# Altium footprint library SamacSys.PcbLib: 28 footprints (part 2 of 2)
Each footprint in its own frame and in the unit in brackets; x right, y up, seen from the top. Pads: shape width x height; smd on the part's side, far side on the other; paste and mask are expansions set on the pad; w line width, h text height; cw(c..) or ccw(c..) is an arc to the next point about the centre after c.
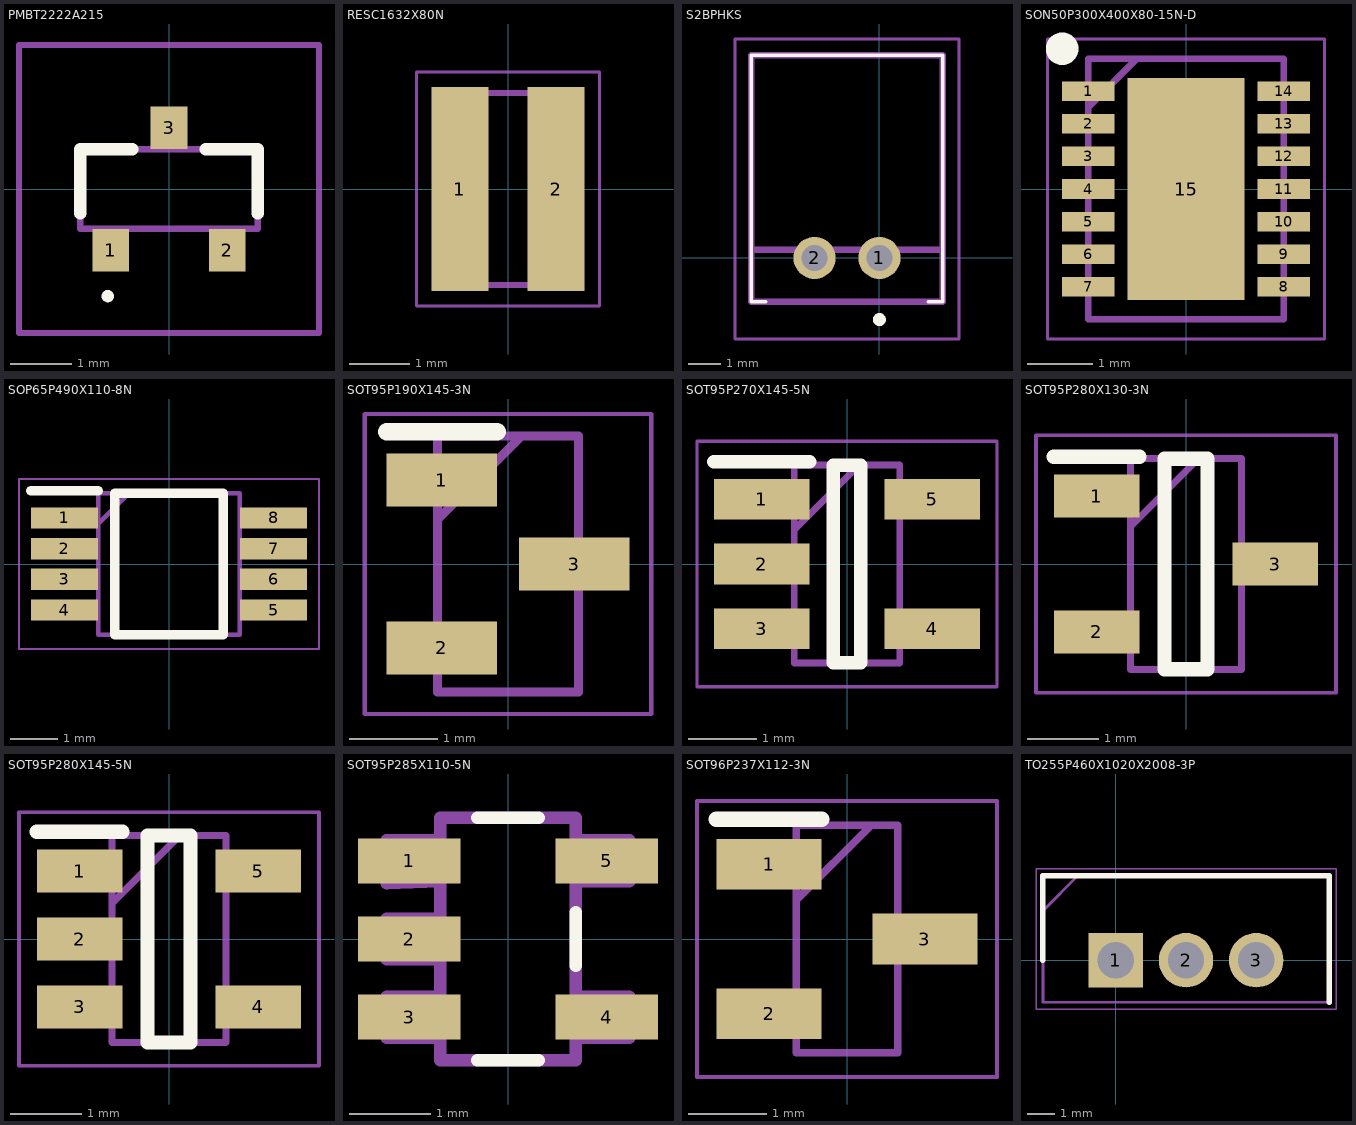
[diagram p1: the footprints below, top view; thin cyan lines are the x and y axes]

## PMBT2222A215 [mm]
pads (3):
  rect 0.6x0.7 smd: 1(-0.95,-1) 2(0.95,-1) 3(0,1)
Top Overlay:
  lines w0.1: -1,-1.8 cw(c-1,-1.75) -1,-1.7 cw(c-1,-1.75) -1,-1.8
  lines w0.2: -1.45,-0.4 -1.45,0.65 -0.6,0.65 ; 0.6,0.65 1.45,0.65 1.45,-0.4
Mechanical 13:
  lines w0.1: -1.45,-0.65 -1.45,0.65 1.45,0.65 1.45,-0.65 -1.45,-0.65
Mechanical 15:
  lines w0.1: -2.45,-2.35 -2.45,2.35 2.45,2.35 2.45,-2.35 -2.45,-2.35
3D body "PMBT2222A,215.stp": height 0.95, standoff 0, extent -1.452,-1.201 1.448,1.199

## RESC1632X80N [mm]
pads (2):
  rect 0.95x3.4 smd: 1(-0.8,0) 2(0.8,0)
Mechanical 13:
  lines w0.1: -0.8,-1.6 -0.8,1.6 0.8,1.6 0.8,-1.6 -0.8,-1.6
Mechanical 15:
  lines w0.05: -1.525,-1.95 -1.525,1.95 1.525,1.95 1.525,-1.95 -1.525,-1.95
3D body "WFCP0612R0150FE66.stp": height 0.8, standoff 0, extent -0.8,-1.6 0.8,1.6

## S2BPHKS [mm]
pads (2):
  round 1.3 hole 0.8: 1(0,0) 2(-2,0)
Top Overlay:
  lines w0.1: -3.5,-1.35 -3.95,-1.35 -3.95,6.25 1.95,6.25 1.95,-1.35 1.5,-1.35
  lines w0.2: -0.1,-1.9 cw(c0,-1.9) 0.1,-1.9 cw(c0,-1.9) -0.1,-1.9
Mechanical 13:
  lines w0.2: -3.95,0.25 -3.95,-1.35 1.95,-1.35 1.95,0.25 ; -3.95,0.25 1.95,0.25 ; -3.95,0.25 -3.95,6.25 1.95,6.25 1.95,0.25 ; -3.95,0.25 1.95,0.25
Mechanical 15:
  lines w0.1: -4.45,-2.5 -4.45,6.75 2.45,6.75 2.45,-2.5 -4.45,-2.5
3D body "S2B-PH-K-S.stp": height 4.9, standoff -5, extent -3.95,-1.35 1.95,6.25

## SON50P300X400X80-15N-D [mm]
pads (15):
  rect 0.8x0.3 smd: 1(-1.5,1.5) 2(-1.5,1) 3(-1.5,0.5) 4(-1.5,0) 5(-1.5,-0.5) 6(-1.5,-1) 7(-1.5,-1.5) 8(1.5,-1.5) 9(1.5,-1) 10(1.5,-0.5) 11(1.5,0) 12(1.5,0.5) 13(1.5,1) 14(1.5,1.5)
  rect 1.8x3.4 smd: 15(0,0)
Top Overlay:
  circle w0.25: c-1.9,2.15 r0.125
Mechanical 13:
  lines w0.1: -1.5,1.25 -0.75,2 ; -1.5,-2 -1.5,2 1.5,2 1.5,-2 -1.5,-2
Mechanical 15:
  lines w0.05: -2.125,-2.3 -2.125,2.3 2.125,2.3 2.125,-2.3 -2.125,-2.3
3D body "LTC3533EDE#TRPBF.stp": height 0.8, standoff 0, extent -1.55,-2 1.55,2

## SOP65P490X110-8N [mm]
pads (8):
  rect 1.425x0.45 smd: 1(-2.212,0.975) 2(-2.212,0.325) 3(-2.212,-0.325) 4(-2.212,-0.975) 5(2.212,-0.975) 6(2.212,-0.325) 7(2.212,0.325) 8(2.212,0.975)
Top Overlay:
  lines w0.2: -2.925,1.55 -1.5,1.55 ; -1.15,-1.5 -1.15,1.5 1.15,1.5 1.15,-1.5 -1.15,-1.5
Mechanical 13:
  lines w0.1: -1.5,0.85 -0.85,1.5 ; -1.5,-1.5 -1.5,1.5 1.5,1.5 1.5,-1.5 -1.5,-1.5
Mechanical 15:
  lines w0.05: -3.175,-1.8 -3.175,1.8 3.175,1.8 3.175,-1.8 -3.175,-1.8
3D body "DS2745U+.stp": height 1.1, standoff 0, extent -2.452,-1.5 2.452,1.5

## SOT95P190X145-3N [mm]
pads (3):
  rect 1.25x0.6 smd: 1(-0.75,0.95) 2(-0.75,-0.95) 3(0.75,0)
Top Overlay:
  lines w0.2: -1.375,1.5 -0.125,1.5
Mechanical 13:
  lines w0.1: -0.8,0.5 0.15,1.45 ; -0.8,-1.45 -0.8,1.45 0.8,1.45 0.8,-1.45 -0.8,-1.45
Mechanical 15:
  lines w0.05: -1.625,-1.7 -1.625,1.7 1.625,1.7 1.625,-1.7 -1.625,-1.7
3D body "HT7750A_SOT23-3.stp": height 1.1, standoff 0, extent -1.3,-1.35 1.3,1.35

## SOT95P270X145-5N [mm]
pads (5):
  rect 1.4x0.6 smd: 1(-1.25,0.95) 2(-1.25,0) 3(-1.25,-0.95) 4(1.25,-0.95) 5(1.25,0.95)
Top Overlay:
  lines w0.2: -1.95,1.5 -0.55,1.5 ; -0.2,-1.45 -0.2,1.45 0.2,1.45 0.2,-1.45 -0.2,-1.45
Mechanical 13:
  lines w0.1: -0.775,0.5 0.175,1.45 ; -0.775,-1.45 -0.775,1.45 0.775,1.45 0.775,-1.45 -0.775,-1.45
Mechanical 15:
  lines w0.05: -2.2,-1.8 -2.2,1.8 2.2,1.8 2.2,-1.8 -2.2,-1.8
3D body "MCP73831T-2ACI_OT.stp": height 1.45, standoff 0, extent -1.35,-1.45 1.35,1.45

## SOT95P280X130-3N [mm]
pads (3):
  rect 1.2x0.6 smd: 1(-1.25,0.95) 2(-1.25,-0.95) 3(1.25,0)
Top Overlay:
  lines w0.2: -1.85,1.5 -0.65,1.5 ; -0.3,-1.475 -0.3,1.475 0.3,1.475 0.3,-1.475 -0.3,-1.475
Mechanical 13:
  lines w0.1: -0.775,0.525 0.175,1.475 ; -0.775,-1.475 -0.775,1.475 0.775,1.475 0.775,-1.475 -0.775,-1.475
Mechanical 15:
  lines w0.05: -2.1,-1.8 -2.1,1.8 2.1,1.8 2.1,-1.8 -2.1,-1.8
3D body "TSM2312CX_RFG.stp": height 1.3, standoff 0, extent -1.4,-1.475 1.4,1.475

## SOT95P280X145-5N [mm]
pads (5):
  rect 1.2x0.6 smd: 1(-1.25,0.95) 2(-1.25,0) 3(-1.25,-0.95) 4(1.25,-0.95) 5(1.25,0.95)
Top Overlay:
  lines w0.2: -1.85,1.5 -0.65,1.5 ; -0.3,-1.45 -0.3,1.45 0.3,1.45 0.3,-1.45 -0.3,-1.45
Mechanical 13:
  lines w0.1: -0.8,0.5 0.15,1.45 ; -0.8,-1.45 -0.8,1.45 0.8,1.45 0.8,-1.45 -0.8,-1.45
Mechanical 15:
  lines w0.05: -2.1,-1.775 -2.1,1.775 2.1,1.775 2.1,-1.775 -2.1,-1.775
3D body "TPS76333DBVT.stp": height 1.2, standoff 0, extent -1.4,-1.45 1.4,1.45

## SOT95P285X110-5N [mil]
pads (5):
  rect 50x22 smd: 1(-48,38) 2(-48,0) 3(-48,-38) 4(48,-38) 5(48,38)
Top Overlay:
  lines w6: -15,-59 15,-59 ; -15,59 15,59 ; 33,-13 33,13
Mechanical 13:
  lines w6: -59,-48 -59,-28 -33,-28 -33,-48 -59,-48 ; -59,-10 -59,10 -33,10 -33,-10 -59,-10 ; -59,27 -59,48 -33,48 -33,28 -59,27 ; -33,-59 33,-59 33,59 -33,59 -33,-59 ; 33,-48 33,-28 59,-28 59,-48 33,-48 ; 33,28 33,48 59,48 59,28 33,28

## SOT96P237X112-3N [mm]
pads (3):
  rect 1.35x0.65 smd: 1(-1,0.96) 2(-1,-0.96) 3(1,0)
Top Overlay:
  lines w0.2: -1.675,1.535 -0.325,1.535
Mechanical 13:
  lines w0.1: -0.65,0.5 0.31,1.46 ; -0.65,-1.46 0.65,-1.46 0.65,1.46 -0.65,1.46 -0.65,-1.46
Mechanical 15:
  lines w0.05: -1.925,-1.77 1.925,-1.77 1.925,1.77 -1.925,1.77 -1.925,-1.77

## TO255P460X1020X2008-3P [mm]
pads (3):
  rect 1.98x1.98 hole 1.32: 1(0,0)
  round 1.98 hole 1.32: 2(2.55,0) 3(5.1,0)
Top Overlay:
  lines w0.2: -2.65,0 -2.65,3.07 7.75,3.07 7.75,-1.53
Mechanical 13:
  lines w0.1: -2.65,1.795 -1.375,3.07 ; -2.65,-1.53 -2.65,3.07 7.75,3.07 7.75,-1.53 -2.65,-1.53
Mechanical 15:
  lines w0.05: -2.9,-1.78 -2.9,3.32 8,3.32 8,-1.78 -2.9,-1.78
3D body "LF33CV.stp": height 19.21, standoff -18.2, extent -2.55,-1.53 7.65,3.07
